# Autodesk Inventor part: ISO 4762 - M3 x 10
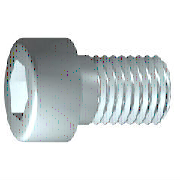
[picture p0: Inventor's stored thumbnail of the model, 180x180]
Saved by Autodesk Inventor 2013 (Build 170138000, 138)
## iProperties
Created: 2012-02
Part Number: ISO 4762 - M3 x 10
Material: Edelstahl, 440C
Description: Innensechskantschraube
Document SubType Name: Modeling
Standard: ISO 4762
Designer: Ente
Standard Revision: 1998
Standards Organization: DIN
Language: de-DE
Size Designation: M3 x 10
Categories: <MemberInstance><Categories><Category DisplayName="Verbindungselemente" InternalName="e4da775c-781d-43d5-af7c-5136215cf5a6" Mnemonic="FSTN"><Category DisplayNam
Density: 7.75 g/cm^3
IsCustomPart: 0
Author: Ente
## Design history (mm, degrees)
sketch "Skizze1"
  geometry: L1 (-0.867, 0)-(10, 0); L2 (10, 0)-(10, 1.5); L3 (10, 1.5)-(1.25, 1.5); L4 (1.25, 1.5)-(0.943, 1.5); L5 (0.943, 1.5)-(0, 1.5); L6 (0, 1.5)-(0, 2.75); L7 (0, 2.75)-(-3, 2.75); L8 (-3, 2.75)-(-3, 1.443); L9 (-3, 1.443)-(-1.7, 1.443); L10 (-1.7, 1.443)-(-0.867, 0); L11 (-5.6, 0)-(12.6, 0) reference; L12 (0, -0.55)-(0, 3.3) reference; L13 (1.25, 1.5)-(0, 1.5)
  constraints: 22 end point, 6 parallel, 2 collinear, 2 perpendicular, 1 horizontal, 1 point on line
  dimensions: "d1" = 8.75 distance from line of L3.end L2 (= GEL); "d2" = 0.30683 distance of L4.end L3.end (computed from GAL); "d3" = 3 distance between parallel lines of L8 L6 (= KOH); "d4" = 1.3 distance of L8.end L9.end (= INTI); "d5" = 60 deg angle of L10 L1; "d6" = 3 diameter of L3 L1 (= GD); "d7" = 3 diameter of L5 L1 (= BDM); "d8" = 2.88675 diameter of L9 L1 (= 1.1547 x SW); "d9" = 5.5 diameter of L7 L1 (= KOD); "d26" = 10 distance between parallel lines of L12 L2 (= NLG)
revolve "Körper" sketch "Skizze1" stored, may be unused: angle "d10" = 90 deg
sketch "Skizze2"
  geometry: L1 (0, -3.85)-(0, 3.85) reference; L2 (-3.85, 0)-(3.85, 0) reference; L3 (1.443, 0)-(0.722, -1.25); L4 (0.722, -1.25)-(-0.722, -1.25); L5 (-0.722, -1.25)-(-1.443, 0); L6 (-1.443, 0)-(-0.722, 1.25); L7 (-0.722, 1.25)-(0.722, 1.25); L8 (0.722, 1.25)-(1.443, 0); 2 further points
  constraints: 12 end point, 1 coincident, 1 horizontal alignment, 1 point on line, 12 other
extrude "Loch" join sketch "Skizze2" stored distance "d11" = 10; taper "d12" = 0 deg
workplane "Work Plane1"
fillet "Fillet2" dims "d30" = 0.1 (= R)
body "Solid1"
fillet "Rundung1" dims "d17" = 0.3 (= RR)
feature "Gewinde" dims "d13" = 8.75 (= GEL), "d14" = 0
chamfer "Fase1" distance "d15" = 0.30673 (= -0.5 x SPD + 0.5 x GD); stored, may be unused: second distance "d16" = 0.30673 (= GUL), angle "d27" = 45 deg
other parameters: "GD" = 3 [user parameter; used in 2 equation terms], "NLG" = 10 [user parameter; used in 1 equation term], "GEL" = 8.75 [user parameter; used in 2 equation terms], "KOD" = 5.5 [user parameter; used in 1 equation term], "KOH" = 3 [user parameter; used in 1 equation term], "INTI" = 1.3 [user parameter; used in 1 equation term], "GAL" = 0.30673 (= 0.61345 x PTC) [user parameter; used in 1 equation term], "GUL" = 0.30673 (= 0.61345 x PTC) [user parameter; used in 1 equation term], "BDM" = 3 (= NND) [user parameter; used in 1 equation term], "SW" = 2.5 [user parameter; used in 2 equation terms], "RR" = 0.3 [user parameter; used in 1 equation term], "SPD" = 2.38655 (= NND - 1.2269 x PTC) [user parameter; used in 1 equation term], "d19" = 0, "d28" = 0, "d29" = 0, "R" = 0.1 [user parameter; used in 1 equation term], "TOA" = 30 deg [user parameter], "GD1" = 2.38655 (= THREADDIA - 1.2269 x PTC) [user parameter], "THREADDIA" = 3 [user parameter; used in 1 equation term], "FAWI" = 45 deg [user parameter], "PTC" = 0.5 [user parameter; used in 5 equation terms], "NND" = 3 [user parameter; used in 2 equation terms], "E0" = 2.8875 (= 1.155 x SW) [user parameter]
